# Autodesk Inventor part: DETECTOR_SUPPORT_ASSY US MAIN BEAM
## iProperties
Shininess: 64.0
Length Units: 11272
Angle Units: 11279
Time Units: 11290
Mass Units: 11286
Length Display Precision: 3
Angle Display Precision: 2
Compacted: True
Part Number: DETECTOR_SUPPORT_ASSY US MAIN BEAM
Document SubType Name: Modeling
Created: 2004-08
Designer: John Blackburn
Material: MILD_STEEL
Manufacturer: Standard
Standards Organization: Custom
Density: 0.0
Volumn: 0.0
Area: 0.0
PropertySet Name: Model Information
Control State: 0
Master: False
Checked Out: False
Author: John Blackburn
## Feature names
1. ExtrusionMidplane1
2. ExtrusionThru1
3. ExtrusionThru2
4. ExtrusionThru3
5. ExtrusionThru4
6. ExtrusionThru5
7. ExtrusionThru6
8. ExtrusionThru7
9. ExtrusionBlind1
